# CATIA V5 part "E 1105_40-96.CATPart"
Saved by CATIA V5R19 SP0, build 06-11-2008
Definition: E 1105_40-96
Nomenclature: E 1105_40-96
Description: PART--DESC
Material "Brass": density 8216 kg/m3, Young's modulus 1.31e+11 Pa, Poisson ratio 0.35, thermal expansion 1.67e-05 1/K
Bounding box of the stored display mesh (mm): x 249.5 to 308.5, y -258.49 to -199.51, z -172 to -66
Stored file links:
  G:\UTB\Kombinované\Bakalářská práce\Catia\FORMA\E 1105_40-96.CATPart
  D:\Aplikace\CATIA\Nová složka\win_b64\startup\materials\Catalog.CATMaterial
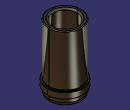
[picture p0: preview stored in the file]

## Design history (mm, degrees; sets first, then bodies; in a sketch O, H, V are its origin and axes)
Body1 "E 1105_40-96" (main body)
  Solid1: solid without history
